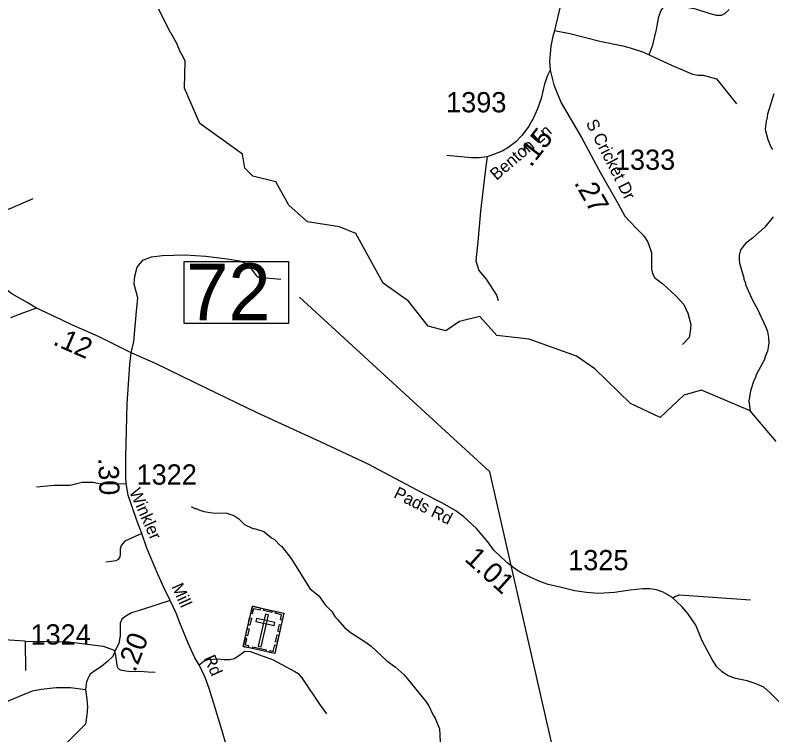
# Model space of a CAD drawing. Extents: x 1248089 to 1457196, y 820910 to 988753.
# Drawn here: x 1346272 to 1350937, y 883995 to 888434 of the extents above; entities that cross this region are included whole.
import ezdxf

# ---------------------------------------------------------------- set-up
doc = ezdxf.new("R2010")
doc.units = 0
for name, color, linetype in [('Exist Cultural Cemetery CELL', 7, 'Continuous'), ('Exist Hydrographic Creek Single Shore', 7, 'Continuous'), ('Exist Hydrographic Misc Water Feature', 7, 'Continuous'), ('Exist Road Non-System Type 51', 7, 'Continuous'), ('Exist Road Secondary Structure Standard Bridge Number Label', 7, 'Continuous'), ('Exist Road Secondary Type 51 Attributed', 7, 'Continuous'), ('Exist Road Secondary Type 51 Label', 7, 'Continuous'), ('Prop GRAU CAT1 Cell', 7, 'Continuous'), ('Prop Lane Lines', 7, 'Continuous')]:
    doc.layers.add(name, color=color, linetype=linetype)

msp = doc.modelspace()

# ---------------------------------------------------------------- linework, layer by layer
at = {"layer": 'Exist Cultural Cemetery CELL'}
for points in [[(1347734.6, 884788.5), (1347928.7, 884744.5), (1347872.3, 884496.1), (1347678.2, 884540.2)], [(1347725, 884746.3), (1347736.1, 884743.8), (1347743.2, 884775.2), (1347782.7, 884766.2), (1347785.2, 884777), (1347734.6, 884788.5)], [(1347834.4, 884735.8), (1347816.2, 884740), (1347771.3, 884542.2), (1347789.5, 884538.1)], [(1347806.8, 884772.1), (1347857.3, 884760.6), (1347854.8, 884749.5), (1347804.3, 884761)], [(1347919.2, 884702.1), (1347908.1, 884704.7), (1347915.3, 884736.1), (1347875.7, 884745), (1347878.2, 884755.9), (1347928.8, 884744.4)], [(1347708.6, 884674), (1347718.1, 884716.2), (1347729.2, 884713.7), (1347719.7, 884671.5)], [(1347759.3, 884713.1), (1347755.2, 884694.9), (1347870, 884668.8), (1347874.1, 884687.1)], [(1347693.7, 884608.4), (1347703.2, 884650.7), (1347714.3, 884648.2), (1347704.8, 884605.9)], [(1347891.9, 884633.4), (1347901.5, 884675.7), (1347912.6, 884673.1), (1347903, 884630.9)], [(1347877.3, 884569.1), (1347886.8, 884611.4), (1347898, 884608.8), (1347888.4, 884566.6)], [(1347710.5, 884533), (1347713, 884544.2), (1347691.6, 884549), (1347700.5, 884588.4), (1347689.6, 884590.9), (1347678.2, 884540.3)], [(1347736.8, 884538.7), (1347819.5, 884519.9), (1347817, 884508.8), (1347734.2, 884527.6)], [(1347840, 884503.5), (1347842.6, 884514.7), (1347864, 884509.8), (1347873, 884549.2), (1347883.8, 884546.8), (1347872.3, 884496.1)]]:
    msp.add_lwpolyline(points, close=True, dxfattribs=at)
at = {"layer": 'Exist Hydrographic Creek Single Shore'}
msp.add_lwpolyline([(1350963, 885803.1), (1350802.9, 885992.3), (1350503, 886120.9), (1350394, 886090.2), (1350248.9, 885952), (1350066.9, 886037.7), (1349846.9, 886252.2), (1349732, 886330), (1349441.9, 886434.4), (1349242.9, 886458.1), (1349136.9, 886575.2), (1349010.9, 886544.8), (1348926.9, 886487.4), (1348818.9, 886515.9), (1348696.9, 886669.3), (1348540.9, 886780.9), (1348372.9, 887086.2), (1348272.9, 887127.6), (1348073.9, 887157.9), (1347959.9, 887261.9), (1347878.9, 887404.7), (1347737.8, 887440.4), (1347688.8, 887490.5), (1347674.9, 887576.2), (1347411.9, 887765.3), (1347316.9, 887984), (1347321.2, 888149.3)], dxfattribs=at)
at = {"layer": 'Exist Hydrographic Misc Water Feature'}
for points in [[(1347155.2, 888471.9), (1347226.2, 888330.2), (1347231, 888327.3), (1347264.7, 888265.4), (1347291.3, 888200.7), (1347295.9, 888197.9), (1347321.2, 888149.3)], [(1350949.9, 887949.1), (1350911, 887822.1), (1350906.3, 887790.2), (1350902.1, 887782.2), (1350897, 887728.4), (1350911.6, 887666), (1350930.6, 887621.6), (1350942.2, 887605.3)], [(1350945, 887189.3), (1350893.6, 887126.4), (1350818.1, 887058.1), (1350775.4, 887025.1), (1350744.5, 886985.9), (1350735.8, 886954.1), (1350735.1, 886924), (1350738.7, 886903.9), (1350764.6, 886813.4), (1350764.5, 886805.4), (1350775.9, 886781.1), (1350775.8, 886773.1), (1350817.6, 886676.1), (1350848.4, 886619.4), (1350900, 886510.2), (1350911.4, 886482.1), (1350916.6, 886445.9), (1350917.7, 886409.9), (1350910.6, 886362), (1350893.8, 886322.4), (1350893.6, 886314.4), (1350839.4, 886211.7), (1350839.2, 886203.7), (1350826.7, 886180), (1350805.2, 886116.4), (1350795.8, 886052.7), (1350802.9, 885992.3)], [(1347357.3, 885403.3), (1347381, 885390.7), (1347389, 885390.6), (1347404.8, 885382.2), (1347436.5, 885373.4), (1347488.4, 885364.2), (1347576.4, 885362.3), (1347620.1, 885347.2), (1347651.5, 885326.5), (1347686.8, 885291.7), (1347742.3, 885266.4), (1347748.6, 885267.3), (1347805.8, 885249), (1347853, 885209.9), (1347870.7, 885199.6), (1347905.9, 885162.7), (1347913.8, 885158.5), (1347974.2, 885083.2), (1348090.1, 884898.5), (1348145.1, 884853.2), (1348183.9, 884796.3), (1348225, 884755.4), (1348242.3, 884725.1), (1348259, 884705.7), (1348304.7, 884655.5), (1348344, 884624.7), (1348430.8, 884568.7), (1348466.2, 884542), (1348564.2, 884451.6), (1348615.4, 884414.5), (1348670.3, 884365.2), (1348806.6, 884198.2), (1348822.1, 884173.8), (1348848.8, 884117.2), (1348860.5, 884102.9), (1348888.2, 884031.6), (1348893.1, 883952.1)]]:
    msp.add_lwpolyline(points, dxfattribs=at)
at = {"layer": 'Exist Road Non-System Type 51'}
for points in [[(1350180.8, 888189.4), (1350202.6, 888251.4), (1350226, 888344), (1350241.3, 888424.9), (1350255.3, 888462.4), (1350269.4, 888483.5), (1350294, 888490.5), (1350333.8, 888490.5), (1350392.4, 888487), (1350467.3, 888472.9), (1350548.1, 888446), (1350593.8, 888433.1), (1350626.6, 888434.3), (1350647.7, 888443.6), (1350674.6, 888468.3)], [(1349597.3, 888339.3), (1349691.2, 888320.6), (1349877.4, 888272.6), (1350017.9, 888243.3), (1350064.8, 888232.7), (1350146.8, 888205.8), (1350180.8, 888189.4)], [(1350180.8, 888189.4), (1350322.5, 888122.5), (1350391.2, 888093.5), (1350447.4, 888068.9), (1350481.4, 888064.2), (1350514.2, 888064.2), (1350595.1, 888040.1), (1350719.9, 887887.1)], [(1349083.9, 887552.7), (1348933.6, 887567.6)], [(1349181.7, 887559.5), (1349173.3, 887501.1), (1349141.6, 887225.5), (1349123.9, 887034.6), (1349113.3, 886918), (1349131, 886858), (1349176.9, 886805), (1349240.4, 886706), (1349251, 886674.2)], [(1346173.8, 887215.3), (1346255.8, 887247.1), (1346382.9, 887302.8)], [(1346988.3, 886351.4), (1347003.2, 886420.8), (1347020.9, 886608.1), (1347028, 886689.4), (1347006.8, 886774.2), (1347010.3, 886823.6), (1347024.4, 886880.2), (1347059.7, 886922.6), (1347112.7, 886943.8), (1347179.8, 886950.8), (1347321, 886954.4), (1347448.1, 886947.3), (1347578.8, 886929.6), (1347656.5, 886919), (1347691.8, 886904.9), (1347716.5, 886883.7), (1347758.9, 886827.2), (1347773, 886816.6), (1347910.7, 886806)], [(1350215.4, 886812.7), (1350264.4, 886776.7), (1350345.6, 886702.5), (1350395.1, 886649.5), (1350419.8, 886596.5), (1350437.4, 886525.8), (1350433.9, 886479.9), (1350426.8, 886445.6), (1350387.4, 886403.2)], [(1346404, 885525.2), (1346513.5, 885535.8), (1346612.4, 885535.8), (1346686.5, 885553.5), (1346753.6, 885553.5), (1346796, 885542.9), (1346956.1, 885544.1)], [(1347052.4, 885237.5), (1346947.7, 885189.2), (1346925.3, 885163.3), (1346919.4, 885139.8), (1346919.4, 885108), (1346917.1, 885093.8), (1346907.7, 885076.2), (1346892.4, 885069.1), (1346832.4, 885059.7)], [(1350324.5, 884836.9), (1350338.6, 884849.2), (1350368.5, 884858), (1350602.2, 884842.2), (1350806, 884828.1)], [(1346334.3, 884572.7), (1346102.5, 884586.9), (1345963, 884591.6)], [(1346334.3, 884572.7), (1346603.9, 884568), (1346814.4, 884541.9), (1346889.7, 884515.7)], [(1346334.3, 884572.7), (1346336.7, 884392.8)], [(1347136, 884379.6), (1347092, 884382.5), (1347036.1, 884385.6), (1346992, 884384.5), (1346954.1, 884387.3), (1346930.1, 884391.7), (1346918.2, 884396), (1346906.4, 884408.2), (1346900.8, 884424.4), (1346897.4, 884456.4), (1346894, 884484.5), (1346884.5, 884512.7)], [(1347406.3, 884426), (1347438.1, 884450.7), (1347462.8, 884460.1), (1347521.6, 884464.8), (1347560.5, 884459), (1347594.6, 884459), (1347624, 884466), (1347658.2, 884488.4), (1347687.6, 884510.8), (1347724.1, 884509.6), (1347773.5, 884490.8), (1347859.4, 884459), (1347997.1, 884385.9), (1348017.2, 884373), (1348040.7, 884347.1), (1348152.5, 884177.4), (1348191.4, 884125.6)], [(1346149.8, 884172.7), (1346379.2, 884267.4), (1346433.6, 884276.9), (1346525.9, 884286.3), (1346613.4, 884286.3), (1346707, 884274.2)], [(1346707.1, 884061.5), (1346452.5, 883810.6)]]:
    msp.add_lwpolyline(points, dxfattribs=at)
at = {"layer": 'Exist Road Secondary Structure Standard Bridge Number Label'}
msp.add_lwpolyline([(1347314.2, 886914.3), (1347958.3, 886914.3), (1347958.3, 886532), (1347314.2, 886532)], close=True, dxfattribs=at)
msp.add_lwpolyline([(1349770.7, 883110.6), (1349199.7, 885616.6), (1348026, 886695.1)], dxfattribs=at)
at = {"layer": 'Exist Road Secondary Type 51 Attributed'}
for points in [[(1349141.4, 889300.2), (1349196.8, 889195.8), (1349239.5, 889122.7), (1349327.6, 889020.7), (1349436.4, 888931.2), (1349546.6, 888822.3), (1349604.2, 888765.1), (1349624.9, 888727.9), (1349641.4, 888683.8), (1349649, 888627), (1349648.3, 888565.3), (1349642.8, 888532.2), (1349597.3, 888339.3), (1349584.9, 888293.3), (1349575.3, 888242.3), (1349567, 888148.6), (1349571.2, 888093.5)], [(1349571.2, 888093.5), (1349554.4, 888060.6), (1349536.5, 888009.6), (1349514.5, 887918.6), (1349492.5, 887856.6), (1349467.7, 887800.1), (1349438.8, 887747.8), (1349397.5, 887694), (1349358.9, 887652.7), (1349309.7, 887616), (1349273.9, 887594), (1349221.6, 887573.3), (1349181.7, 887559.5), (1349133.5, 887552.7), (1349083.9, 887552.7)], [(1349571.2, 888093.5), (1349573.9, 888077), (1349593, 888003.4), (1349638.5, 887893.1), (1349763.8, 887679.5), (1349883.5, 887456.8), (1349989.5, 887270.7), (1350032, 887194.1), (1350059.6, 887162.4), (1350106.4, 887112.8), (1350147.7, 887072.8), (1350171.1, 887037), (1350187.6, 886994.2), (1350194.4, 886970), (1350195.7, 886931.4), (1350194.4, 886866.7), (1350201.6, 886840.3), (1350215.4, 886812.7)], [(1346403.7, 886627.4), (1346345.8, 886660.5), (1346251.9, 886713.8), (1346172.9, 886774.1), (1346106.7, 886844.3), (1346056.7, 886895.1), (1345927.3, 887041.4), (1345891.8, 887087.9), (1345835.4, 887171.9), (1345801.1, 887230.6), (1345678.6, 887361.1), (1345585.8, 887471.8), (1345507.9, 887595.8), (1345440.7, 887742.1), (1345397.2, 887858.7), (1345369.6, 887953.3), (1345359.8, 888019.4)], [(1346403.7, 886627.4), (1346324.7, 886597.8), (1346243.7, 886566.1)], [(1346988.3, 886351.4), (1346786.5, 886451.8), (1346625.5, 886522), (1346557.3, 886553.6), (1346403.7, 886627.4)], [(1347227.2, 884822.8), (1347189.3, 884903.2), (1347152.9, 884986.7), (1347084.9, 885146.6), (1347052.4, 885237.5), (1347019.8, 885322.6), (1346969.8, 885472.8), (1346956.1, 885544.1), (1346954.6, 885586.5), (1346954.6, 885709.6), (1346963.7, 886037.2), (1346980.4, 886279.9), (1346988.3, 886351.4)], [(1350984.9, 884197.5), (1350923, 884258.1), (1350887, 884288.3), (1350833.5, 884312.2), (1350784.3, 884329.1), (1350713.9, 884343.2), (1350664.7, 884360.1), (1350630.9, 884382.6), (1350598.5, 884413.6), (1350570.4, 884460.1), (1350507.3, 884575), (1350467.9, 884672.2), (1350418.6, 884742.6), (1350382, 884786.2), (1350320.6, 884843.6), (1350267.2, 884874.6), (1350226.4, 884888.7), (1350184.1, 884895.7), (1350141.9, 884895.7), (1350064.5, 884887.3), (1349967.4, 884873.2), (1349869.5, 884866.1), (1349794.9, 884873.1), (1349723.1, 884883), (1349641.5, 884902.7), (1349558.5, 884922.4), (1349507.8, 884940.7), (1349443.1, 884968.9), (1349391, 884994.2), (1349357.3, 885016.8), (1349313.6, 885050.6), (1349271.4, 885088.6), (1349224.1, 885133.1), (1349186.1, 885185.3), (1349115.7, 885266.9), (1349038.6, 885339.9), (1348989.4, 885376.5), (1348907.8, 885422.9), (1348782.5, 885487.7), (1348449.6, 885664.7), (1348154.1, 885802.8), (1347917, 885910.6), (1347760.8, 885983.9), (1347454, 886131.7), (1347137.4, 886285.2), (1346988.3, 886351.4)], [(1347227.2, 884822.8), (1347058.4, 884768.9), (1346989.9, 884746.6), (1346954.9, 884727.5), (1346931.1, 884708.4), (1346919.9, 884682.9), (1346919.9, 884606.4), (1346912, 884558.7), (1346889.7, 884515.7), (1346875.4, 884479), (1346843.5, 884448.8), (1346805.3, 884416.9), (1346764, 884389.8), (1346734, 884368.2), (1346726.1, 884355.4), (1346711.7, 884322), (1346707, 884274.2), (1346713.3, 884215.3), (1346718.2, 884166.6), (1346713.4, 884118.8), (1346707.1, 884061.5)], [(1348487.4, 882544.8), (1348340, 882659.8), (1348264.4, 882733.4), (1348192.8, 882809.1), (1348151, 882866.8), (1348089.7, 882967.4), (1348028, 883080.9), (1347972.3, 883180.4), (1347870.9, 883359.5), (1347714, 883641.1), (1347630.5, 883794.3), (1347600.6, 883856.1), (1347576.8, 883919.7), (1347547, 884026.7), (1347503.3, 884168), (1347469.4, 884281.5), (1347443.6, 884349.2), (1347406.3, 884426), (1347379.9, 884470.6), (1347338.2, 884560.2), (1347288.5, 884685.6), (1347264.6, 884745.3), (1347227.2, 884822.8)]]:
    msp.add_lwpolyline(points, dxfattribs=at)

# ---------------------------------------------------------------- texts
at = {"layer": 'Exist Road Secondary Structure Standard Bridge Number Label'}
msp.add_text('72', height=350, dxfattribs=at).set_placement((1347326.7, 886551.8))
at = {"layer": 'Exist Road Secondary Type 51 Label'}
for s, rotation, p in [('S Cricket Dr', 296.9336, (1349788.9, 887768.5)), ('Benton Ln', 40.5844, (1349239.6, 887411)), ('Winkler           Mill            Rd', 294.0885, (1346973.8, 885495.2)), ('Pads Rd', 333.1888, (1348600.6, 885461.6))]:
    msp.add_text(s, height=75, rotation=rotation, dxfattribs=at).set_placement(p)
at = {"layer": 'Prop GRAU CAT1 Cell'}
for s, rotation, p in [('.15', 52.4539, (1349452.2, 887490.9)), ('.27', 299.6794, (1349715.5, 887399.6)), ('.12', 336.4461, (1346499.5, 886403.8)), ('.30', 272.0439, (1346784.4, 885702.4)), ('1.01', 317.9902, (1349037.1, 885072.9)), ('.20', 68.6459, (1347012, 884376.8))]:
    msp.add_text(s, height=125, rotation=rotation, dxfattribs=at).set_placement(p)
at = {"layer": 'Prop Lane Lines'}
for s, p in [('1393', (1348929.1, 887833.9)), ('1333', (1349969.7, 887479.4)), ('1322', (1347020.8, 885538)), ('1325', (1349681.6, 885010)), ('1324', (1346367, 884551.8))]:
    msp.add_text(s, height=125, dxfattribs=at).set_placement(p)

doc.saveas('drawing.dxf')
